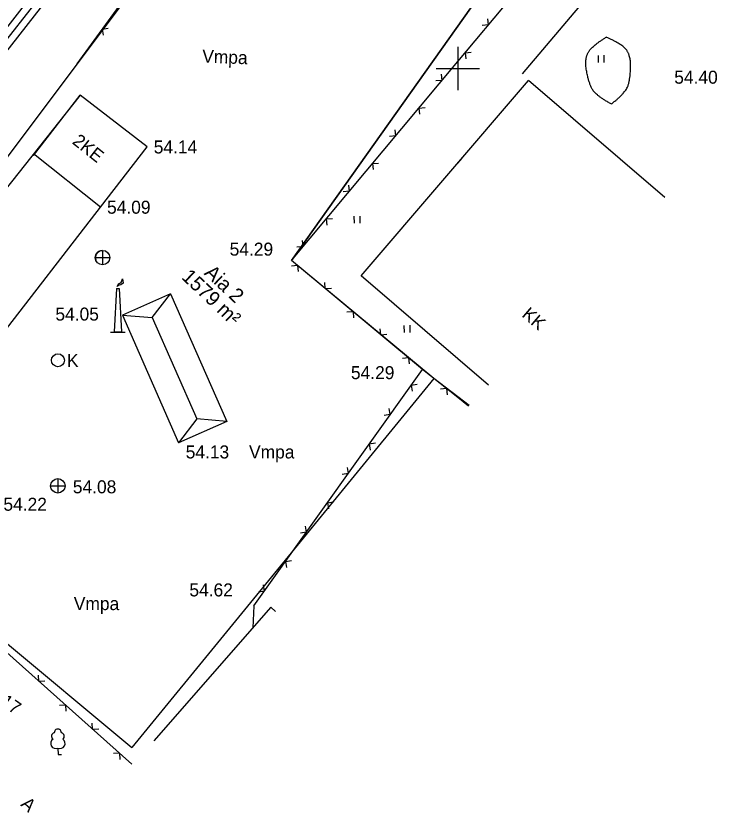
# Model space of a CAD drawing. Extents: x -2270 to -2134, y 846 to 969.
# Drawn here: x -2193 to -2144.4, y 850.1 to 905.2 of the extents above; entities that cross this region are included whole.
import ezdxf

# ---------------------------------------------------------------- set-up
doc = ezdxf.new("R2010")
doc.units = 0
for name, color, linetype in [('Level 10', 7, 'Continuous'), ('Level 11', 7, 'Continuous'), ('Level 16', 7, 'Continuous'), ('Level 18', 7, 'Continuous'), ('Level 21', 7, 'Continuous'), ('Level 4', 7, 'Continuous'), ('Level 45', 7, 'Continuous'), ('Level 6', 7, 'Continuous'), ('Level 63', 7, 'Continuous'), ('Level 7', 7, 'Continuous'), ('Level 9', 7, 'Continuous')]:
    doc.layers.add(name, color=color, linetype=linetype)

# ---------------------------------------------------------------- blocks, each defined once
blk = doc.blocks.new('HAKA')
at = {"layer": 'Level 63'}
for q in [(-0.012, 0.012), (0.012, 0.012)]:
    blk.add_line((0, 0), q, dxfattribs=at)
blk = doc.blocks.new('41')
at = {"layer": 'Level 63'}
for p, q in [((-0.00772, -0.00991), (-0.00772, 0.01009)), ((0.00828, -0.00991), (0.00828, 0.01009))]:
    blk.add_line(p, q, dxfattribs=at)
blk = doc.blocks.new('16')
at = {"layer": 'Level 63'}
for p, q in [((0, 0.06), (0, -0.06)), ((-0.06, 0), (0.06, 0))]:
    blk.add_line(p, q, dxfattribs=at)
blk = doc.blocks.new('81')
at = {"layer": 'Level 63'}
for p, q in [((-0.02, 0), (0.02, 0)), ((0, 0.02), (0, -0.02))]:
    blk.add_line(p, q, dxfattribs=at)
blk.add_circle((0, 0), 0.02, dxfattribs=at)
blk = doc.blocks.new('31')
at = {"layer": 'Level 63'}
for p, q in [((0, 0.0176), (0, 0)), ((0, 0), (0.0096, 0))]:
    blk.add_line(p, q, dxfattribs=at)
for centre, radius, start, end in [((0, 0.06), 0.01, 359.8604, 180.8406), ((-0.0074, 0.0502), 0.01, 104.8801, 233.1553), ((0.0079, 0.0502), 0.01, 304.5704, 78.153), ((-0.006, 0.0303), 0.014, 122.2165, 294.8474), ((0.0058, 0.0303), 0.014, 245.1526, 56.0466)]:
    blk.add_arc(centre, radius, start, end, dxfattribs=at)
blk = doc.blocks.new('413')
at = {"layer": 'Level 63'}
blk.add_text('Vmpa', height=0.036, dxfattribs=at).set_placement((-0.00017, 0.00106))
blk = doc.blocks.new('410')
at = {"layer": 'Level 63'}
blk.add_text('A', height=0.036, dxfattribs=at).set_placement((-0.00087, 0.00021))

msp = doc.modelspace()

# ---------------------------------------------------------------- linework, layer by layer
at = {"layer": 'Level 10'}
for p, q in [((-2180.377, 913.395), (-2188.744, 901.892)), ((-2162.369, 902.057), (-2157.213, 908.223)), ((-2186.995, 904.297), (-2186.576, 904.363)), ((-2186.995, 904.297), (-2186.929, 903.878)), ((-2173.883, 888.286), (-2162.369, 902.057)), ((-2164.812, 880.753), (-2173.883, 888.286)), ((-2176.481, 864.399), (-2164.812, 880.753)), ((-2162.369, 878.798), (-2164.812, 880.753)), ((-2161.624, 878.201), (-2162.369, 878.798)), ((-2184.942, 853.431), (-2198.898, 865.889)), ((-2176.481, 864.399), (-2176.551, 862.877))]:
    msp.add_line(p, q, dxfattribs=at)
at = {"layer": 'Level 11'}
for p, q in [((-2186.96, 888.989), (-2186.967, 887.989)), ((-2187.463, 888.493), (-2186.463, 888.486)), ((-2190.048, 881.385), (-2190.048, 881.385))]:
    msp.add_line(p, q, dxfattribs=at)
for centre, radius in [((-2186.963, 888.489), 0.5), ((-2190.048, 881.385), 0.45)]:
    msp.add_circle(centre, radius, dxfattribs=at)
at = {"layer": 'Level 18'}
msp.add_line((-2187.463, 888.493), (-2187.311, 888.492), dxfattribs=at)
msp.add_arc((-2186.963, 888.489), 0.5, 93.2762, 201.2328, dxfattribs=at)
at = {"layer": 'Level 21'}
for p, q in [((-2207.864, 886.227), (-2188.912, 910.359)), ((-2207.466, 885.925), (-2188.549, 910.016)), ((-2207.068, 885.622), (-2188.185, 909.673))]:
    msp.add_line(p, q, dxfattribs=at)
at = {"layer": 'Level 45'}
for p, q in [((-2195.519, 892.834), (-2173.639, 921.954)), ((-2159.019, 909.234), (-2173.879, 888.284)), ((-2173.879, 888.284), (-2159.019, 909.234)), ((-2230.947, 892.878), (-2184.939, 854.594)), ((-2164.039, 880.114), (-2173.879, 888.284)), ((-2164.039, 880.114), (-2184.939, 854.594)), ((-2161.584, 878.244), (-2164.039, 880.114))]:
    msp.add_line(p, q, dxfattribs=at)
at = {"layer": 'Level 6'}
for p, q in [((-2169.053, 887.223), (-2157.471, 900.735)), ((-2148.03, 892.642), (-2157.471, 900.735)), ((-2188.502, 899.738), (-2199.532, 885.847)), ((-2191.734, 895.567), (-2188.502, 899.738)), ((-2183.87, 896.148), (-2188.502, 899.738)), ((-2187.102, 891.977), (-2183.87, 896.148)), ((-2187.102, 891.977), (-2191.74, 895.66)), ((-2162.369, 895.021), (-2162.066, 895.375)), ((-2194.734, 882.129), (-2187.102, 891.977)), ((-2162.369, 881.494), (-2169.053, 887.223)), ((-2185.577, 887.028), (-2185.575, 887.03)), ((-2186.002, 886.358), (-2186.152, 883.358)), ((-2186.002, 886.358), (-2185.802, 886.358)), ((-2186.002, 886.356), (-2186, 886.357)), ((-2185.802, 886.358), (-2185.652, 883.358)), ((-2182.255, 885.984), (-2185.589, 884.517)), ((-2183.519, 884.335), (-2182.255, 885.984)), ((-2182.255, 885.984), (-2178.365, 877.143)), ((-2185.589, 884.517), (-2181.7, 875.676)), ((-2185.589, 884.517), (-2183.519, 884.335)), ((-2183.519, 884.335), (-2180.435, 877.325)), ((-2186.402, 883.339), (-2185.402, 883.339)), ((-2186.152, 883.358), (-2185.652, 883.358)), ((-2160.242, 879.67), (-2162.369, 881.494)), ((-2180.435, 877.325), (-2181.7, 875.676)), ((-2178.365, 877.143), (-2181.7, 875.676)), ((-2178.365, 877.143), (-2180.435, 877.325)), ((-2175.311, 864.29), (-2183.419, 855.048)), ((-2174.987, 864.005), (-2175.311, 864.29))]:
    msp.add_line(p, q, dxfattribs=at)
msp.add_lwpolyline([(-2185.946, 886.485), (-2185.869, 886.673), (-2185.684, 886.767), (-2185.576, 887.031), (-2185.545, 886.73), (-2185.699, 886.617), (-2185.823, 886.579), (-2185.946, 886.485)], dxfattribs=at)
at = {"layer": 'Level 7'}
msp.add_line((-2146.968, 914.186), (-2157.904, 901.206), dxfattribs=at)
at = {"layer": 'Level 9'}
for points in [[(-2151.749, 899.121), (-2152.89, 899.734), (-2153.355, 900.78), (-2153.587, 902.232), (-2153.122, 903.103), (-2152.101, 903.747)], [(-2151.749, 899.121), (-2150.714, 899.9), (-2150.413, 901.004), (-2150.403, 902.474), (-2150.994, 903.265), (-2152.101, 903.747)]]:
    msp.add_open_spline(points, degree=2, dxfattribs=at)

# ---------------------------------------------------------------- block references
at = {"layer": 'Level 10'}
for p, xscale, yscale, rotation in [((-2160.252, 904.588), 25, 25.000000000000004, 50.099399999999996), ((-2161.856, 902.671), 25, 25, -129.90060000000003), ((-2163.46, 900.753), 25, 25, 50.09939999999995), ((-2165.063, 898.835), 25, 25, -129.90060000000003), ((-2166.667, 896.917), 25, 25, 50.09939999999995), ((-2168.271, 894.999), 25, 25, -129.90060000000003), ((-2169.874, 893.081), 25, 25, 50.09939999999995), ((-2171.478, 891.163), 25, 25, -129.90060000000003), ((-2173.081, 889.245), 25, 25, 50.09939999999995), ((-2173.467, 887.941), 25, 25, 140.29199999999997), ((-2171.544, 886.343), 25, 25, -39.70800000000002), ((-2169.62, 884.746), 25, 25, 140.29199999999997), ((-2167.697, 883.149), 25, 25, -39.70800000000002), ((-2165.774, 881.552), 25, 25, 140.29199999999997), ((-2165.591, 879.662), 25.000000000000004, 24.999999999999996, -125.50860000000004), ((-2163.152, 879.424), 25.000000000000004, 24.999999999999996, 141.33149999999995), ((-2167.043, 877.627), 24.999999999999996, 25, 54.491399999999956), ((-2168.495, 875.592), 25.000000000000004, 24.999999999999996, -125.50860000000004), ((-2169.947, 873.557), 24.999999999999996, 25, 54.491399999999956), ((-2171.399, 871.522), 25.000000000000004, 24.999999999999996, -125.50860000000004), ((-2172.851, 869.487), 24.999999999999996, 25, 54.491399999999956), ((-2174.303, 867.452), 25.000000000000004, 24.999999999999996, -125.50860000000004), ((-2175.755, 865.417), 24.999999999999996, 25, 54.491399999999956), ((-2191.382, 859.18), 24.999999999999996, 25.000000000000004, -41.75280000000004), ((-2189.517, 857.515), 24.999999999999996, 25.000000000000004, 138.24720000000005), ((-2187.652, 855.85), 24.999999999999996, 25.000000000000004, -41.75280000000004), ((-2185.787, 854.186), 24.999999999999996, 25.000000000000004, 138.24720000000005)]:
    msp.add_blockref('HAKA', p, dxfattribs=dict(at, xscale=xscale, yscale=yscale, rotation=rotation))
at = {"layer": 'Level 11', "xscale": 25.000000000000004, "yscale": 25, "rotation": -0.3346770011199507}
msp.add_blockref('81', (-2190.057, 872.692), dxfattribs=at)
at = {"layer": 'Level 16', "xscale": 25, "yscale": 25}
msp.add_blockref('16', (-2162.369, 901.574), dxfattribs=at)
msp.add_blockref('16', (-2162.369, 901.574), dxfattribs=at)
at = {"layer": 'Level 7', "xscale": 25, "yscale": 25, "rotation": -42.62182543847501}
msp.add_blockref('410', (-2192.669, 850.574), dxfattribs=at)
at = {"layer": 'Level 9', "xscale": 25, "yscale": 24.999999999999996}
for name, p, rotation in [('41', (-2152.444, 902.237), 0.9245153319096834), ('41', (-2169.338, 891.113), 0.9245153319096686), ('41', (-2165.882, 883.551), 0.9245153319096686), ('31', (-2190.046, 854.11), 0.4297865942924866)]:
    msp.add_blockref(name, p, dxfattribs=dict(at, rotation=rotation))
at = {"layer": 'Level 9', "xscale": 25, "yscale": 25}
for p in [(-2176.817, 874.563), (-2188.947, 864.068)]:
    msp.add_blockref('413', p, dxfattribs=at)

# ---------------------------------------------------------------- texts
at = {"layer": 'Level 11'}
msp.add_text('K', height=0.9, rotation=0.2165, dxfattribs=at).set_placement((-2189.424, 880.919))
at = {"layer": 'Level 4'}
for s, p in [('54.40', (-2147.387, 900.525)), ('54.14', (-2183.42, 895.698)), ('54.09', (-2186.652, 891.527)), ('54.29', (-2178.165, 888.625)), ('54.05', (-2190.226, 884.132)), ('54.29', (-2169.77, 880.078)), ('54.13', (-2181.207, 874.591)), ('54.08', (-2189.02, 872.177)), ('54.22', (-2193.826, 870.971)), ('54.62', (-2180.951, 865.043))]:
    msp.add_text(s, height=0.9, dxfattribs=at).set_placement(p)
msp.add_text('54.17', height=0.9, rotation=325.6096, dxfattribs=at).set_placement((-2195.487, 858.526))
at = {"layer": 'Level 45'}
for s, p in [('1579 m²', (-2181.554, 887.076)), ('Aia 2', (-2179.975, 887.361))]:
    msp.add_text(s, height=1, rotation=316.7303, dxfattribs=at).set_placement(p)
at = {"layer": 'Level 6'}
for s, rotation, p in [('2KE', 321.5479, (-2189.115, 896.42)), ('KK', 319.3975, (-2157.994, 884.453))]:
    msp.add_text(s, height=0.9, rotation=rotation, dxfattribs=at).set_placement(p)
at = {"layer": 'Level 9'}
msp.add_text('Vmpa', height=0.9, rotation=357.8462, dxfattribs=at).set_placement((-2180.075, 901.986))

doc.saveas('drawing.dxf')
